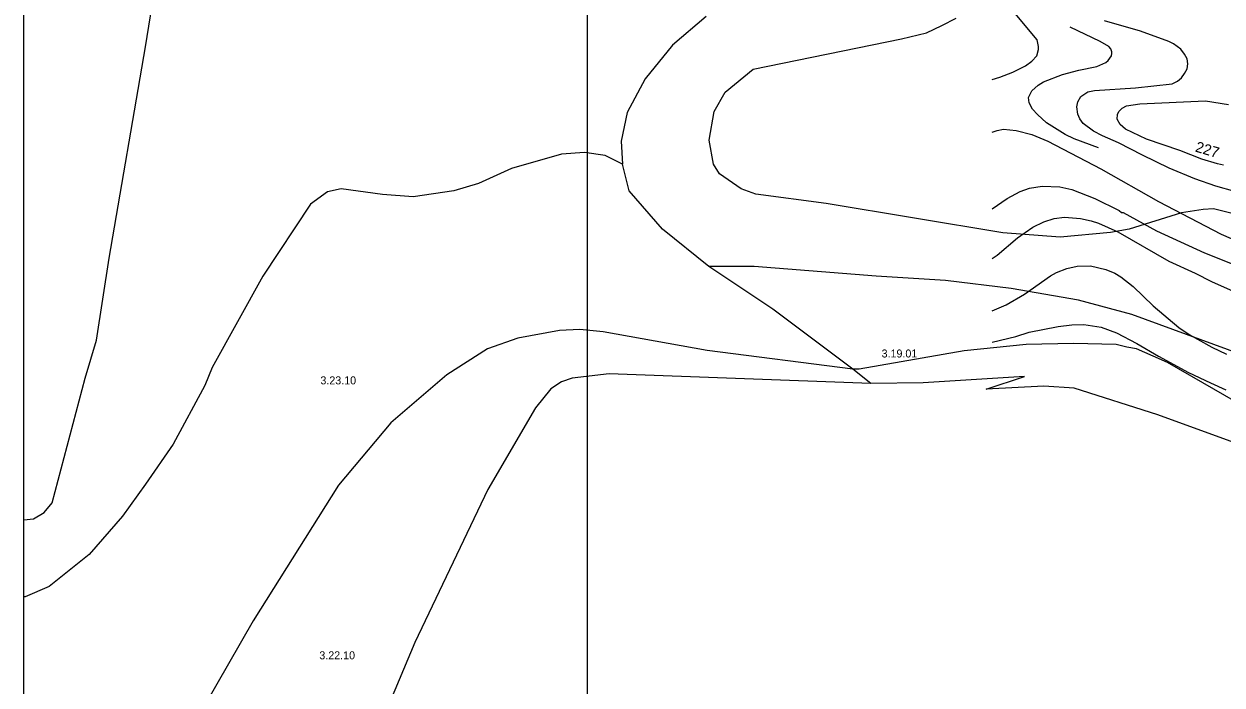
# Model space of a CAD drawing. Extents: x -662500 to -653478, y -1056827 to -1049993.
# Drawn here: x -662500 to -661377, y -1053980 to -1053360 of the extents above; entities that cross this region are included whole.
import ezdxf

# ---------------------------------------------------------------- set-up
doc = ezdxf.new("R2010")
doc.units = 0
for name, color, linetype in [('Vrstva 24', 7, 'Continuous'), ('Vrstva 7', 7, 'Continuous'), ('Vrstva 9', 7, 'Continuous')]:
    doc.layers.add(name, color=color, linetype=linetype)

msp = doc.modelspace()

# ---------------------------------------------------------------- linework, layer by layer
at = {"layer": 'Vrstva 24'}
for points in [[(-662500, -1053824.9), (-662500, -1053023.2)], [(-662500, -1053824.9), (-662491, -1053824), (-662481, -1053818), (-662473.5, -1053809), (-662442.5, -1053692), (-662432, -1053656.5), (-662420, -1053579.5), (-662386, -1053381.5), (-662375, -1053313.5), (-662363.5, -1053210.5), (-662350.5, -1053159.3)], [(-661860.5, -1053353), (-661892, -1053380), (-661917.5, -1053411.5), (-661934.5, -1053443), (-661940, -1053470), (-661939, -1053491.5)], [(-661366, -1053538), (-661385, -1053533.5), (-661394.5, -1053534), (-661415, -1053537), (-661464, -1053552.5), (-661481.5, -1053555.5), (-661528.5, -1053560), (-661582.5, -1053556), (-661748, -1053528.5), (-661814, -1053519.5), (-661827.5, -1053514.5), (-661848, -1053500.5), (-661853.5, -1053491.5), (-661857.5, -1053469), (-661853, -1053442), (-661842.5, -1053424), (-661816.5, -1053402.5), (-661677.5, -1053374), (-661654, -1053368.5), (-661639.5, -1053361.5), (-661626, -1053354.5)], [(-661939, -1053491.5), (-661955, -1053483.5), (-661974.5, -1053480.5), (-661996, -1053482), (-662043, -1053495.5), (-662074, -1053509.5), (-662097, -1053516.5), (-662135, -1053522), (-662164, -1053520), (-662202.5, -1053514.5), (-662215.5, -1053517.5), (-662231.5, -1053529), (-662276, -1053596.5), (-662323.5, -1053682), (-662330.5, -1053699), (-662360, -1053754), (-662386, -1053791.5), (-662407.5, -1053821.5), (-662439, -1053857.5), (-662476.5, -1053887.5), (-662499, -1053897), (-662500, -1053897.1)], [(-661858, -1053587.5), (-661901.5, -1053552.5), (-661932.5, -1053516.5), (-661939, -1053491.5)], [(-661723, -1053683.5), (-661798, -1053627.5), (-661858, -1053587.5)], [(-661185.5, -1053695), (-661301, -1053684), (-661359, -1053670), (-661461.5, -1053632.5), (-661511.5, -1053619), (-661574.5, -1053608), (-661636, -1053600.5), (-661701, -1053596.5), (-661815.5, -1053587.5), (-661858, -1053587.5)], [(-661723, -1053683.5), (-661859.5, -1053666), (-661957, -1053648.5), (-661979, -1053646.5), (-661998, -1053647.5), (-662037, -1053654.5), (-662065.5, -1053664.5), (-662103.5, -1053689), (-662156, -1053734), (-662205, -1053792.5), (-662285, -1053919.5), (-662331.5, -1054000), (-662360.5, -1054035.5), (-662385.5, -1054080.5), (-662405, -1054139), (-662415.5, -1054202), (-662415, -1054265), (-662409, -1054319), (-662411, -1054350.5), (-662415, -1054362.5)], [(-661001.5, -1053773), (-661007, -1053832.5), (-661011, -1053841.5), (-661017, -1053844.5), (-661056, -1053821), (-661089.5, -1053807), (-661175, -1053776.5), (-661238, -1053757.5), (-661296.5, -1053744), (-661341, -1053727.5), (-661428, -1053677.5), (-661441.5, -1053671.5), (-661457, -1053664.5), (-661466, -1053663), (-661476, -1053660.5), (-661516, -1053659.5), (-661560.5, -1053660.5), (-661618.5, -1053666.5), (-661717, -1053683.5), (-661723, -1053683.5)], [(-661706, -1053697), (-661723, -1053683.5)], [(-661706, -1053697), (-661951.5, -1053688), (-661986, -1053692), (-661996, -1053695.5), (-662006, -1053702), (-662020.5, -1053720), (-662065, -1053796.5), (-662133.5, -1053940), (-662158.8, -1054000)], [(-661246.7, -1054000), (-661255.5, -1053914.5), (-661259, -1053855.5), (-661241.5, -1053852), (-661175.5, -1053833), (-661167, -1053828.5), (-661160, -1053819.5), (-661160.5, -1053809.5), (-661167, -1053798.5), (-661180.5, -1053790.5), (-661197, -1053787.5), (-661206.5, -1053790), (-661238, -1053823), (-661261, -1053803.5), (-661278, -1053785.5), (-661300.5, -1053776), (-661437, -1053726.5), (-661515.5, -1053701.5), (-661544, -1053699.5), (-661598, -1053702.5), (-661562, -1053690.5), (-661657, -1053696.5), (-661706, -1053697)], [(-662500, -1053897.1), (-662500, -1053824.9)], [(-662500, -1054302.2), (-662500, -1054000), (-662500, -1053897.1)]]:
    msp.add_lwpolyline(points, dxfattribs=at)
at = {"layer": 'Vrstva 7'}
for p, q in [((-661550.2, -1053374.9), (-661592.2, -1053324.6)), ((-661453.2, -1053366.9), (-661487, -1053357)), ((-661491.2, -1053376.4), (-661519.1, -1053363.1)), ((-661426.7, -1053376.4), (-661453.2, -1053366.9)), ((-661548.8, -1053381.3), (-661550.2, -1053374.9)), ((-661483.1, -1053381.3), (-661491.2, -1053376.4)), ((-661422.4, -1053378.7), (-661426.7, -1053376.4)), ((-661415.6, -1053383.8), (-661422.4, -1053378.7)), ((-661555.3, -1053395), (-661550.6, -1053389.8)), ((-661550.6, -1053389.8), (-661548.9, -1053384.1)), ((-661548.9, -1053384.1), (-661548.8, -1053381.3)), ((-661481, -1053383.4), (-661483.1, -1053381.3)), ((-661481.9, -1053392.1), (-661480.6, -1053389.8)), ((-661480.3, -1053386.1), (-661481, -1053383.4)), ((-661480.6, -1053389.8), (-661480.1, -1053387.7)), ((-661480.1, -1053387.7), (-661480.3, -1053386.1)), ((-661411.9, -1053388.3), (-661415.6, -1053383.8)), ((-661409.7, -1053392.9), (-661411.9, -1053388.3)), ((-661573.1, -1053405.2), (-661561.2, -1053399.3)), ((-661561.2, -1053399.3), (-661555.3, -1053395)), ((-661511.1, -1053403.4), (-661494.1, -1053399.8)), ((-661494.1, -1053399.8), (-661485.7, -1053396.3)), ((-661485.7, -1053396.3), (-661483.5, -1053394.3)), ((-661483.5, -1053394.3), (-661481.9, -1053392.1)), ((-661411.9, -1053406.5), (-661409.6, -1053402)), ((-661409, -1053397.4), (-661409.7, -1053392.9)), ((-661409.6, -1053402), (-661409, -1053397.4)), ((-661592.2, -1053412.1), (-661585.3, -1053410)), ((-661585.3, -1053410), (-661573.1, -1053405.2)), ((-661544.1, -1053414.3), (-661526.4, -1053407.6)), ((-661526.4, -1053407.6), (-661511.1, -1053403.4)), ((-661423.5, -1053416.1), (-661418.7, -1053413.7)), ((-661418.7, -1053413.7), (-661415, -1053410.5)), ((-661415, -1053410.5), (-661411.9, -1053406.5)), ((-661558.3, -1053429), (-661555.1, -1053422.6)), ((-661555.1, -1053422.6), (-661549.3, -1053417.3)), ((-661549.3, -1053417.3), (-661544.1, -1053414.3)), ((-661509.2, -1053428), (-661502.6, -1053423.8)), ((-661502.6, -1053423.8), (-661496.3, -1053422.4)), ((-661496.3, -1053422.4), (-661458.1, -1053419.8)), ((-661458.1, -1053419.8), (-661423.5, -1053416.1)), ((-661557.7, -1053434), (-661558.3, -1053429)), ((-661554.7, -1053439.8), (-661557.7, -1053434)), ((-661513.1, -1053437.7), (-661512.2, -1053433.1)), ((-661512.2, -1053433.1), (-661509.2, -1053428)), ((-661466.3, -1053436.7), (-661454, -1053434.8)), ((-661454, -1053434.8), (-661392.3, -1053432.1)), ((-661392.3, -1053432.1), (-661370.8, -1053435.7)), ((-661550, -1053445), (-661554.7, -1053439.8)), ((-661541.4, -1053452.7), (-661550, -1053445)), ((-661512.1, -1053444.5), (-661513.1, -1053437.7)), ((-661510.1, -1053449), (-661512.1, -1053444.5)), ((-661475.2, -1053449.3), (-661474.8, -1053444.8)), ((-661474.8, -1053444.8), (-661473.7, -1053442.1)), ((-661473.7, -1053442.1), (-661470.5, -1053439.1)), ((-661470.5, -1053439.1), (-661466.3, -1053436.7)), ((-661587.6, -1053459.9), (-661581.6, -1053458.8)), ((-661581.6, -1053458.8), (-661569.7, -1053459.8)), ((-661523.8, -1053463.7), (-661541.4, -1053452.7)), ((-661507.1, -1053453.3), (-661510.1, -1053449)), ((-661497.5, -1053460.5), (-661507.1, -1053453.3)), ((-661472.5, -1053454.2), (-661475.2, -1053449.3)), ((-661467.3, -1053458.6), (-661472.5, -1053454.2)), ((-661447.6, -1053468.1), (-661467.3, -1053458.6)), ((-661592.2, -1053461.5), (-661587.6, -1053459.9)), ((-661569.7, -1053459.8), (-661555.1, -1053463.6)), ((-661555.1, -1053463.6), (-661540.3, -1053470)), ((-661540.3, -1053470), (-661490.4, -1053495.9)), ((-661515.6, -1053467.6), (-661523.8, -1053463.7)), ((-661492.8, -1053476.2), (-661515.6, -1053467.6)), ((-661489, -1053465), (-661497.5, -1053460.5)), ((-661473.8, -1053471.5), (-661489, -1053465)), ((-661416.4, -1053478.6), (-661447.6, -1053468.1)), ((-661451.3, -1053483.2), (-661473.8, -1053471.5)), ((-661395.7, -1053486.8), (-661416.4, -1053478.6)), ((-661426.3, -1053495.1), (-661451.3, -1053483.2)), ((-661381, -1053491.2), (-661395.7, -1053486.8)), ((-661375.6, -1053492.5), (-661381, -1053491.2)), ((-661490.4, -1053495.9), (-661436.5, -1053526.5)), ((-661402.5, -1053505.1), (-661426.3, -1053495.1)), ((-661566.1, -1053517), (-661557.3, -1053514.1)), ((-661557.3, -1053514.1), (-661545.4, -1053512.1)), ((-661545.4, -1053512.1), (-661528.9, -1053512.6)), ((-661528.9, -1053512.6), (-661517.6, -1053515.2)), ((-661382.7, -1053512.1), (-661402.5, -1053505.1)), ((-661364.8, -1053517.2), (-661382.7, -1053512.1)), ((-661592.2, -1053533.4), (-661578.2, -1053523.8)), ((-661578.2, -1053523.8), (-661566.1, -1053517)), ((-661517.6, -1053515.2), (-661496, -1053523.8)), ((-661496, -1053523.8), (-661473.4, -1053535)), ((-661473.4, -1053535), (-661471.1, -1053536.7)), ((-661471.1, -1053536.7), (-661469.7, -1053536.7)), ((-661469.7, -1053536.7), (-661438.2, -1053553.9)), ((-661436.5, -1053526.5), (-661377.6, -1053557)), ((-661554.1, -1053550.5), (-661543.9, -1053545.4)), ((-661543.9, -1053545.4), (-661534.3, -1053542.4)), ((-661534.3, -1053542.4), (-661524.7, -1053541.1)), ((-661524.7, -1053541.1), (-661509.7, -1053542.5)), ((-661509.7, -1053542.5), (-661499.4, -1053544.7)), ((-661499.4, -1053544.7), (-661492.6, -1053546.8)), ((-661492.6, -1053546.8), (-661474.4, -1053554.9)), ((-661568.5, -1053560.4), (-661554.1, -1053550.5)), ((-661474.4, -1053554.9), (-661426.6, -1053582.4)), ((-661438.2, -1053553.9), (-661393.3, -1053574.6)), ((-661377.6, -1053557), (-661345.8, -1053570.9)), ((-661587.7, -1053576.7), (-661568.5, -1053560.4)), ((-661592.2, -1053579.8), (-661587.7, -1053576.7)), ((-661426.6, -1053582.4), (-661402.1, -1053593.6)), ((-661393.3, -1053574.6), (-661362.8, -1053586.9)), ((-661537.7, -1053596.2), (-661532.2, -1053593)), ((-661532.2, -1053593), (-661522.4, -1053589.3)), ((-661522.4, -1053589.3), (-661512.8, -1053587.2)), ((-661512.8, -1053587.2), (-661500.3, -1053586.8)), ((-661500.3, -1053586.8), (-661485.8, -1053590.2)), ((-661485.8, -1053590.2), (-661477.3, -1053593.8)), ((-661402.1, -1053593.6), (-661386.6, -1053601.6)), ((-661562.1, -1053613.5), (-661537.7, -1053596.2)), ((-661477.3, -1053593.8), (-661471.7, -1053597.1)), ((-661471.7, -1053597.1), (-661460.3, -1053606.2)), ((-661386.6, -1053601.6), (-661352.3, -1053616.7)), ((-661579.1, -1053623.3), (-661562.1, -1053613.5)), ((-661460.3, -1053606.2), (-661441.5, -1053624.4)), ((-661592.2, -1053629), (-661579.1, -1053623.3)), ((-661441.5, -1053624.4), (-661417.3, -1053644.7)), ((-661570.3, -1053652.9), (-661557.8, -1053649)), ((-661557.8, -1053649), (-661530.5, -1053643.7)), ((-661530.5, -1053643.7), (-661517.6, -1053642.2)), ((-661517.6, -1053642.2), (-661506.5, -1053641.7)), ((-661506.5, -1053641.7), (-661490.1, -1053644.3)), ((-661490.1, -1053644.3), (-661475.8, -1053649.7)), ((-661475.8, -1053649.7), (-661456.6, -1053659.6)), ((-661417.3, -1053644.7), (-661407.6, -1053651.2)), ((-661592.2, -1053658.4), (-661570.3, -1053652.9)), ((-661456.6, -1053659.6), (-661436.5, -1053671.4)), ((-661407.6, -1053651.2), (-661386.4, -1053663)), ((-661436.5, -1053671.4), (-661408.2, -1053686.8)), ((-661386.4, -1053663), (-661372.8, -1053669.7)), ((-661408.2, -1053686.8), (-661387.6, -1053696.4)), ((-661387.6, -1053696.4), (-661373.3, -1053703))]:
    msp.add_line(p, q, dxfattribs=at)
at = {"layer": 'Vrstva 9'}
msp.add_line((-661971.6, -1054269.4), (-661971.6, -1050953), dxfattribs=at)

# ---------------------------------------------------------------- texts
at = {"layer": 'Vrstva 24'}
for s, p in [('3.19.01', (-661696, -1053672.7)), ('3.23.10', (-662222.1, -1053697.9)), ('3.22.10', (-662223.1, -1053955.6))]:
    msp.add_text(s, height=7.5, dxfattribs=at).set_placement(p)
at = {"layer": 'Vrstva 7'}
msp.add_text('227', height=10, rotation=343.4032, dxfattribs=at).set_placement((-661402.7, -1053479.5))

doc.saveas('drawing.dxf')
